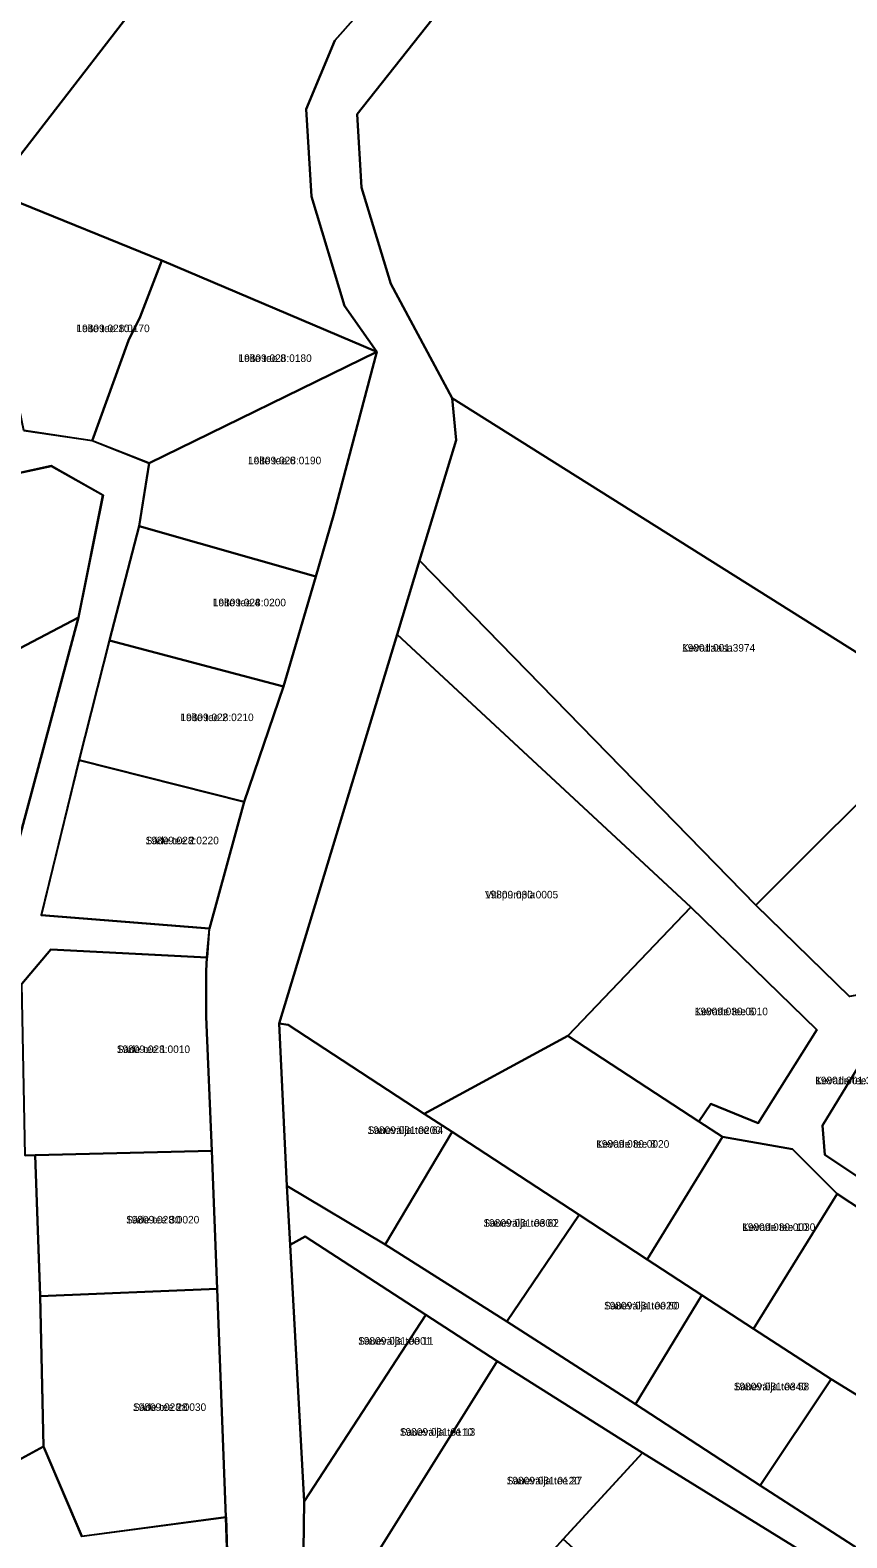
# Model space of a CAD drawing. Extents: x 516875 to 535633, y 6574491 to 6593094.
# Drawn here: x 521647.7 to 521809.5, y 6588659.7 to 6588958.5 of the extents above; entities that cross this region are included whole.
import ezdxf

# ---------------------------------------------------------------- set-up
doc = ezdxf.new("R2010")
doc.units = 0
for name, color, linetype in [('L_AADRESS', 7, 'Continuous'), ('PIIR', 7, 'Continuous'), ('TUNNUS', 7, 'Continuous')]:
    doc.layers.add(name, color=color, linetype=linetype)

msp = doc.modelspace()

# ---------------------------------------------------------------- linework, layer by layer
at = {"layer": 'PIIR'}
for points in [[(521590.91, 6589055.48), (521789.03, 6589241.93), (521800.17, 6589148.45), (521810.31, 6589063.39), (521810.89, 6589058.49), (521811.01, 6589057.49), (521738.69, 6588991.11), (521708.09, 6588956.45), (521702.42, 6588942.89), (521703.42, 6588925.56), (521710, 6588903.9), (521716.38, 6588894.74), (521673.79, 6588912.85), (521643.87, 6588925), (521640.14, 6588926.57), (521679.87, 6588978)], [(521872.18, 6589105.19), (521882.61, 6589104.84), (521905.55, 6589069.27), (521922.81, 6589042.49), (521928.76, 6589039.9), (521963.19, 6589024.91), (521973.32, 6589020.68), (522021.6, 6589004.67), (522038.08, 6588953.13), (522033.81, 6588929.71), (522005.48, 6588915.67), (521984.65, 6588905.34), (521966.56, 6588896.37), (521949.77, 6588888.05), (521931.86, 6588879.17), (521891.39, 6588859.11), (521839.52, 6588833.41), (521829.85, 6588823.63), (521731.32, 6588885.59), (521719.14, 6588908.24), (521713.34, 6588927.32), (521712.5, 6588941.85), (521745.85, 6588984.11), (521847.55, 6589078.97)], [(521526.07, 6589009.51), (521590.91, 6589055.48), (521679.87, 6588978), (521640.14, 6588926.57), (521608.51, 6588906.92)], [(521639.99, 6588910.31), (521643.87, 6588925), (521673.79, 6588912.85), (521669.52, 6588901.71), (521667.19, 6588897.03), (521660, 6588877.16), (521646.47, 6588879.15)], [(521660, 6588877.16), (521667.19, 6588897.03), (521669.52, 6588901.71), (521673.79, 6588912.85), (521716.38, 6588894.74), (521671.31, 6588872.67)], [(521671.31, 6588872.67), (521716.38, 6588894.74), (521707.78, 6588862.33), (521704.29, 6588850.22), (521669.33, 6588860.24)], [(521731.32, 6588885.59), (521829.85, 6588823.63), (521811.4, 6588804.97), (521803.67, 6588797.29), (521791.44, 6588785.11), (521724.86, 6588853.44), (521732.08, 6588877.25)], [(521577.05, 6588827.11), (521579.21, 6588791.46), (521610.2, 6588787.38), (521641.5, 6588783.41), (521657.29, 6588842.15), (521662.14, 6588866.39), (521651.9, 6588872.14), (521639.52, 6588869.47), (521589.17, 6588837.56), (521579.18, 6588830.58), (521578.05, 6588829.6)], [(521614.73, 6588836.16), (521601.26, 6588825), (521589.2, 6588837.49), (521639.54, 6588869.44), (521651.92, 6588872.12), (521662.16, 6588866.37), (521657.31, 6588842.13), (521623.4, 6588824.31)], [(521669.33, 6588860.24), (521704.29, 6588850.22), (521697.93, 6588828.42), (521663.46, 6588837.56)], [(521641.54, 6588783.37), (521610.26, 6588787.33), (521612.66, 6588813.39), (521601.26, 6588825), (521614.73, 6588836.16), (521623.4, 6588824.31), (521657.31, 6588842.13)], [(521663.46, 6588837.56), (521697.93, 6588828.42), (521690.11, 6588805.58), (521657.44, 6588813.85)], [(521720.41, 6588838.75), (521778.59, 6588784.67), (521754.21, 6588759.19), (521725.77, 6588743.75), (521698.85, 6588761.37), (521697.04, 6588761.65)], [(521657.44, 6588813.85), (521690.11, 6588805.58), (521683.24, 6588780.46), (521649.95, 6588783.08)], [(521816.44, 6588768.12), (521810.03, 6588767), (521791.44, 6588785.11), (521803.67, 6588797.29), (521811.4, 6588804.97), (521831.96, 6588782.91)], [(521816.44, 6588760.69), (521816.35, 6588760.6), (521804.67, 6588741.4), (521805.15, 6588735.58), (521824.25, 6588722.94), (521842.63, 6588710.75), (521846.61, 6588711.58), (521860.38, 6588731.68), (521863.88, 6588729.34), (521848.51, 6588706.95), (521869.84, 6588692.8), (521888.66, 6588680.32), (521894.82, 6588681.14), (521909.9, 6588705.32), (521920.48, 6588722.26), (521941.23, 6588755.34), (521918.93, 6588769.74), (521898.61, 6588782.8), (521893.58, 6588774.82), (521856.34, 6588796.43), (521848.08, 6588792.28), (521833.99, 6588778.27)], [(521754.21, 6588759.19), (521778.59, 6588784.67), (521803.58, 6588760.38), (521791.96, 6588741.86), (521782.58, 6588745.74), (521780.21, 6588742.18)], [(521682.74, 6588774.72), (521682.56, 6588772.02), (521682.55, 6588762.98), (521683.71, 6588736.38), (521648.7, 6588735.54), (521646.75, 6588735.49), (521646.08, 6588769.53), (521651.82, 6588776.31)], [(521698.59, 6588729.48), (521697.04, 6588761.65), (521698.85, 6588761.37), (521725.77, 6588743.75), (521731.31, 6588740.16), (521718.06, 6588717.83)], [(521780.21, 6588742.18), (521784.85, 6588739.15), (521769.94, 6588714.83), (521756.48, 6588723.71), (521731.31, 6588740.16), (521725.77, 6588743.75), (521754.21, 6588759.19)], [(521804.67, 6588741.4), (521816.35, 6588760.6), (521838.46, 6588745.92), (521824.25, 6588722.94), (521805.15, 6588735.58)], [(521718.06, 6588717.83), (521731.31, 6588740.16), (521756.48, 6588723.71), (521742.13, 6588702.54)], [(521798.73, 6588736.72), (521807.58, 6588727.9), (521791.01, 6588701.09), (521780.77, 6588707.81), (521769.94, 6588714.83), (521784.85, 6588739.15)], [(521648.7, 6588735.54), (521683.71, 6588736.38), (521684.78, 6588709.02), (521649.68, 6588707.62)], [(521828.46, 6588714.16), (521811.89, 6588687.78), (521806.39, 6588691.14), (521791.01, 6588701.09), (521807.58, 6588727.9)], [(521742.13, 6588702.54), (521756.48, 6588723.71), (521769.94, 6588714.83), (521780.77, 6588707.81), (521767.63, 6588686.2)], [(521702.21, 6588719.4), (521726.13, 6588703.92), (521701.97, 6588666.89), (521699.24, 6588717.74)], [(521650.33, 6588677.78), (521649.68, 6588707.62), (521684.78, 6588709.02), (521686.51, 6588663.81), (521657.96, 6588659.97)], [(521767.63, 6588686.2), (521780.77, 6588707.81), (521791.01, 6588701.09), (521806.39, 6588691.14), (521792.34, 6588670.05)], [(521701.97, 6588666.89), (521726.13, 6588703.92), (521740.2, 6588694.73), (521715.24, 6588654.72), (521705.56, 6588638.88), (521701.69, 6588642.87)], [(521715.24, 6588654.72), (521740.2, 6588694.73), (521768.99, 6588676.54), (521753.3, 6588659.4), (521738.96, 6588643.55), (521733.04, 6588643.34)], [(521792.34, 6588670.05), (521806.39, 6588691.14), (521811.89, 6588687.78), (521828.99, 6588676.38), (521814.85, 6588655.55)], [(521635.57, 6588669.71), (521645.98, 6588675.4), (521650.36, 6588677.81), (521657.98, 6588660.01), (521686.54, 6588663.79), (521687.16, 6588643.42), (521662.53, 6588638.23), (521636.65, 6588632.7)], [(521768.99, 6588676.54), (521806.87, 6588653.15), (521808.19, 6588651.25), (521808.9, 6588648.85), (521809.11, 6588647.83), (521808.15, 6588646.42), (521795.73, 6588627.46), (521767.59, 6588646.53), (521753.3, 6588659.4)]]:
    msp.add_lwpolyline(points, close=True, dxfattribs=at)
for points in [[(521847.55, 6589078.97), (521745.85, 6588984.11), (521712.5, 6588941.85), (521713.34, 6588927.32), (521719.14, 6588908.24), (521731.32, 6588885.59), (521732.08, 6588877.25), (521724.86, 6588853.44), (521720.41, 6588838.75), (521697.04, 6588761.65), (521698.59, 6588729.48), (521699.24, 6588717.74), (521701.97, 6588666.89), (521701.69, 6588642.87)], [(521687.16, 6588643.42), (521686.51, 6588663.81), (521684.78, 6588709.02), (521683.71, 6588736.38), (521682.55, 6588762.98), (521682.56, 6588772.02), (521682.74, 6588774.72), (521683.24, 6588780.46), (521690.11, 6588805.58), (521697.93, 6588828.42), (521704.29, 6588850.22), (521707.78, 6588862.33), (521716.38, 6588894.74), (521710, 6588903.9), (521703.42, 6588925.56), (521702.42, 6588942.89), (521708.09, 6588956.45), (521738.69, 6588991.11), (521811.01, 6589057.49)], [(521646.47, 6588879.18), (521659.98, 6588877.2), (521671.29, 6588872.7), (521669.3, 6588860.26), (521663.44, 6588837.59), (521657.42, 6588813.87), (521649.91, 6588783.1), (521683.19, 6588780.47), (521682.77, 6588774.74), (521651.8, 6588776.32), (521646.05, 6588769.53)], [(521828.46, 6588714.16), (521807.58, 6588727.9), (521798.73, 6588736.72), (521784.85, 6588739.15), (521780.21, 6588742.18), (521782.58, 6588745.74), (521791.96, 6588741.86), (521803.58, 6588760.38), (521778.59, 6588784.67), (521720.41, 6588838.75), (521724.86, 6588853.44), (521791.44, 6588785.11), (521810.03, 6588767)], [(521646.77, 6588735.5), (521648.71, 6588735.56), (521649.69, 6588707.64), (521650.36, 6588677.81), (521645.98, 6588675.4)], [(521806.87, 6588653.15), (521768.99, 6588676.54), (521740.2, 6588694.73), (521726.13, 6588703.92), (521702.21, 6588719.4), (521699.24, 6588717.74), (521698.59, 6588729.48), (521718.06, 6588717.83), (521742.13, 6588702.54), (521767.63, 6588686.2), (521792.34, 6588670.05), (521814.85, 6588655.55)]]:
    msp.add_lwpolyline(points, dxfattribs=at)

# ---------------------------------------------------------------- texts
at = {"layer": 'L_AADRESS'}
for s, p in [('Loite tee 10', (521656.89, 6588898.67)), ('Loite tee 8', (521688.99, 6588892.76)), ('Loite tee 6', (521690.88, 6588872.48)), ('Loite tee 4', (521683.89, 6588844.33)), ('Kevadaasa', (521776.85, 6588835.35)), ('Loite tee 2', (521677.49, 6588821.57)), ('Säde tee 2', (521670.59, 6588797.16)), ('Viti pumpla', (521737.82, 6588786.43)), ('Kevade tee 6', (521779.36, 6588763.27)), ('Säde tee 1', (521664.89, 6588755.78)), ('Kevade tee', (521803.23, 6588749.59)), ('Sauevälja tee 64', (521714.58, 6588739.74)), ('Kevade tee 8', (521759.83, 6588737.01)), ('Säde tee 30', (521666.72, 6588722)), ('Sauevälja tee 62', (521737.51, 6588721.35)), ('Kevade tee 10', (521788.76, 6588720.52)), ('Sauevälja tee 60', (521761.4, 6588704.96)), ('Sauevälja tee 11', (521712.69, 6588697.97)), ('Sauevälja tee 58', (521787.1, 6588688.93)), ('Säde tee 28', (521668.09, 6588684.84)), ('Sauevälja tee 13', (521720.95, 6588679.92)), ('Sauevälja tee 27', (521742.12, 6588670.28))]:
    msp.add_text(s, height=1.5, dxfattribs=at).set_placement(p)
at = {"layer": 'TUNNUS'}
for s, p in [('19809:028:0170', (521656.89, 6588898.67)), ('19809:028:0180', (521688.99, 6588892.76)), ('19809:028:0190', (521690.88, 6588872.48)), ('19809:028:0200', (521683.89, 6588844.33)), ('19801:001:3974', (521776.85, 6588835.35)), ('19809:028:0210', (521677.49, 6588821.57)), ('19809:028:0220', (521670.59, 6588797.16)), ('19809:030:0005', (521737.82, 6588786.43)), ('19809:030:0010', (521779.36, 6588763.27)), ('19809:028:0010', (521664.89, 6588755.78)), ('19801:001:3914', (521803.23, 6588749.59)), ('19809:031:0200', (521714.58, 6588739.74)), ('19809:030:0020', (521759.83, 6588737.01)), ('19809:028:0020', (521666.72, 6588722)), ('19809:031:0300', (521737.51, 6588721.35)), ('19809:030:0030', (521788.76, 6588720.52)), ('19809:031:0020', (521761.4, 6588704.96)), ('19809:031:0001', (521712.69, 6588697.97)), ('19809:031:0340', (521787.1, 6588688.93)), ('19809:028:0030', (521668.09, 6588684.84)), ('19809:031:0110', (521720.95, 6588679.92)), ('19809:031:0120', (521742.12, 6588670.28))]:
    msp.add_text(s, height=1.5, dxfattribs=at).set_placement(p)

doc.saveas('drawing.dxf')
